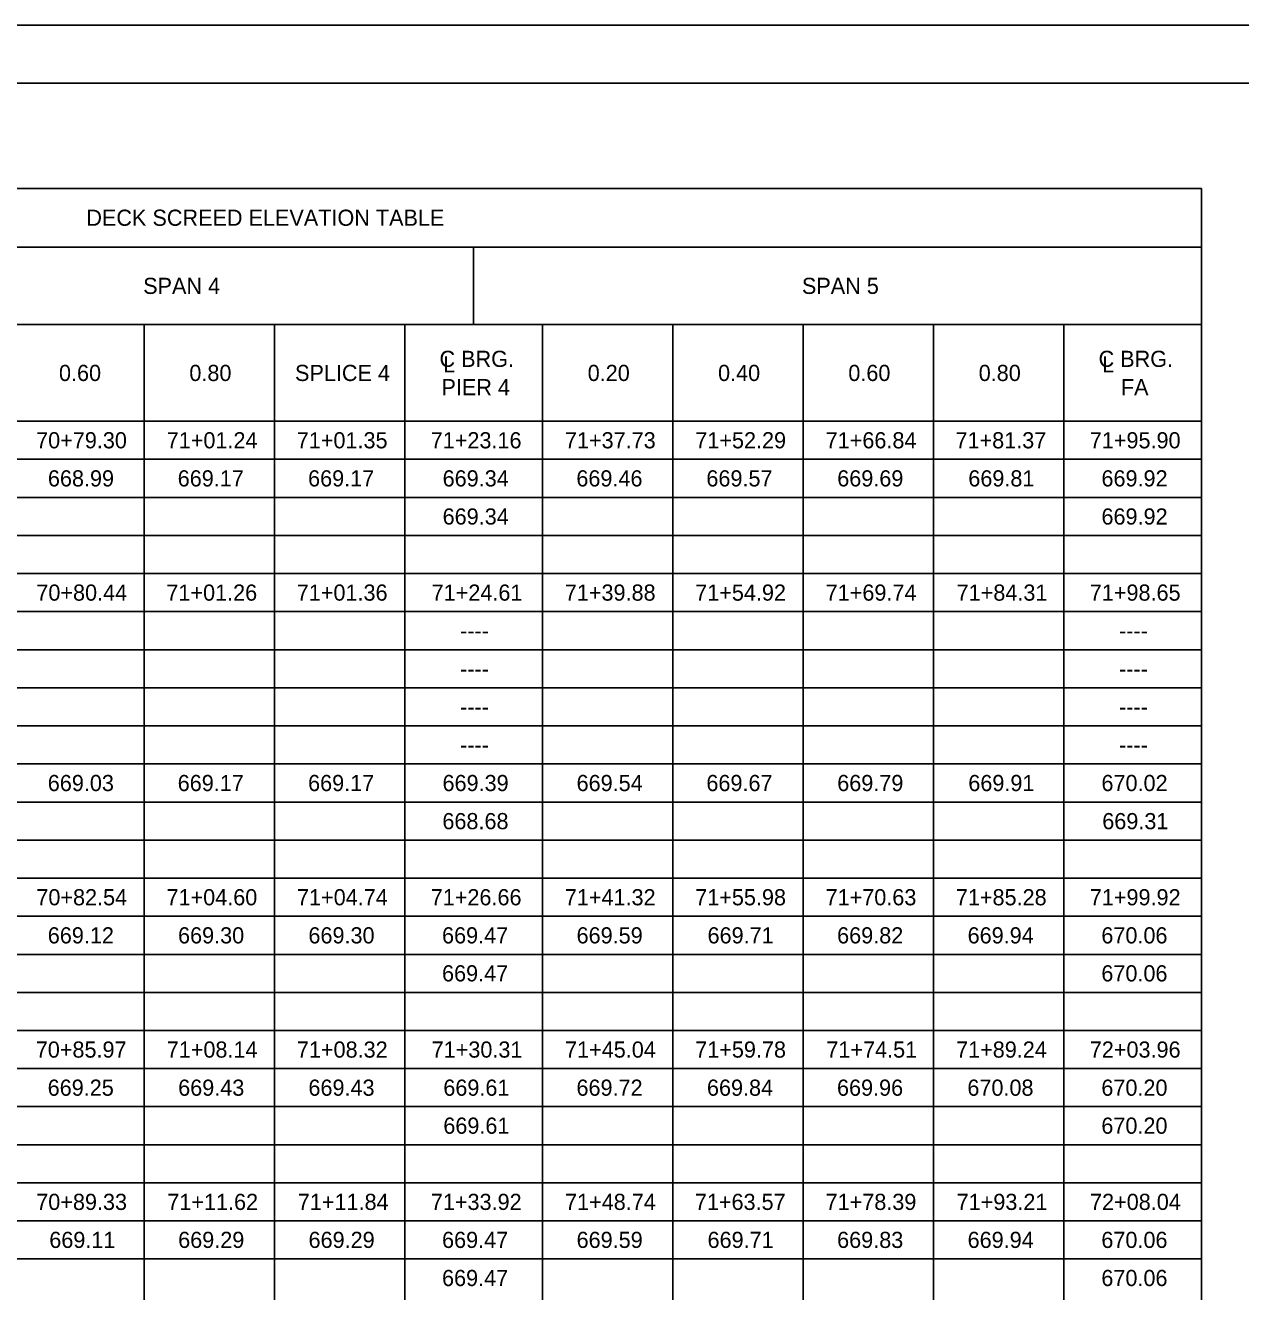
# Model space of a CAD drawing. Extents: x 0 to 34, y 0 to 22.
# Drawn here: x 9.87 to 20.39, y 11.03 to 22 of the extents above; entities that cross this region are included whole.
import ezdxf

# ---------------------------------------------------------------- set-up
doc = ezdxf.new("R2010")
doc.units = 0
for name, color, linetype in [('SH_Border', 7, 'Continuous'), ('SH_Cut_Line', 7, 'Continuous'), ('SH_Text', 7, 'Continuous')]:
    doc.layers.add(name, color=color, linetype=linetype)

msp = doc.modelspace()

# ---------------------------------------------------------------- linework, layer by layer
at = {"layer": 'SH_Border'}
msp.add_lwpolyline([(1.5, 21.5), (33.5, 21.5), (33.5, 0.5), (1.5, 0.5)], close=True, dxfattribs=at)
at = {"layer": 'SH_Cut_Line'}
msp.add_lwpolyline([(0, 0), (34, 0), (34, 22), (0, 22)], close=True, dxfattribs=at)
at = {"layer": 'SH_Text'}
for p, q in [((3.627, 20.588), (20.049, 20.588)), ((20.049, 20.588), (20.049, 1.756)), ((3.627, 20.08), (20.049, 20.08)), ((13.747, 20.08), (13.747, 19.408)), ((3.627, 19.408), (20.049, 19.408)), ((10.894, 19.408), (10.894, 1.756)), ((12.022, 19.408), (12.022, 1.756)), ((13.151, 19.408), (13.151, 1.756)), ((14.343, 19.408), (14.343, 1.756)), ((15.471, 19.408), (15.471, 1.756)), ((16.6, 19.408), (16.6, 1.756)), ((17.729, 19.408), (17.729, 1.756)), ((18.857, 19.408), (18.857, 1.756)), ((3.627, 18.571), (20.049, 18.571)), ((5.022, 18.242), (20.049, 18.242)), ((5.022, 17.912), (20.049, 17.912)), ((3.627, 17.582), (20.049, 17.582)), ((3.627, 17.253), (20.049, 17.253)), ((5.022, 16.923), (20.049, 16.923)), ((5.022, 16.593), (20.049, 16.593)), ((5.022, 16.263), (20.049, 16.263)), ((5.022, 15.934), (20.049, 15.934)), ((5.022, 15.604), (20.049, 15.604)), ((5.022, 15.274), (20.049, 15.274)), ((3.627, 14.945), (20.049, 14.945)), ((3.627, 14.615), (20.049, 14.615)), ((5.022, 14.285), (20.049, 14.285)), ((5.022, 13.955), (20.049, 13.955)), ((3.627, 13.626), (20.049, 13.626)), ((3.627, 13.296), (20.049, 13.296)), ((5.022, 12.966), (20.049, 12.966)), ((5.022, 12.637), (20.049, 12.637)), ((3.627, 12.307), (20.049, 12.307)), ((3.627, 11.977), (20.049, 11.977)), ((5.022, 11.647), (20.049, 11.647)), ((5.022, 11.318), (20.049, 11.318))]:
    msp.add_line(p, q, dxfattribs=at)

# ---------------------------------------------------------------- texts
for s, p in [('DECK SCREED ELEVATION TABLE', (10.394, 20.264)), ('SPAN 4', (10.886, 19.674)), ('SPAN 5', (16.59, 19.674)), ('C BRG.         ', (13.452, 19.042)), ('L', (13.483, 18.995)), ('C BRG.         ', (19.159, 19.042)), ('L', (19.19, 18.995)), ('0.60', (10.157, 18.92)), ('0.80', (11.286, 18.92)), ('SPLICE 4', (12.201, 18.92)), ('0.20', (14.735, 18.92)), ('0.40', (15.864, 18.92)), ('0.60', (16.992, 18.92)), ('0.80', (18.121, 18.92)), ('PIER 4', (13.469, 18.797)), ('FA', (19.352, 18.797)), ('70+79.30', (9.959, 18.337)), ('71+01.24', (11.09, 18.337)), ('71+01.35', (12.216, 18.337)), ('71+23.16', (13.376, 18.337)), ('71+37.73', (14.538, 18.337)), ('71+52.29', (15.667, 18.337)), ('71+66.84', (16.796, 18.337)), ('71+81.37', (17.92, 18.337)), ('71+95.90', (19.083, 18.337)), ('668.99', (10.061, 18.007)), ('669.17', (11.185, 18.007)), ('669.17', (12.314, 18.007)), ('669.34', (13.479, 18.007)), ('669.46', (14.637, 18.007)), ('669.57', (15.763, 18.007)), ('669.69', (16.896, 18.007)), ('669.81', (18.031, 18.007)), ('669.92', (19.184, 18.007)), ('669.34', (13.479, 17.677)), ('669.92', (19.184, 17.677)), ('70+80.44', (9.961, 17.018)), ('71+01.26', (11.087, 17.018)), ('71+01.36', (12.216, 17.018)), ('71+24.61', (13.384, 17.018)), ('71+39.88', (14.537, 17.018)), ('71+54.92', (15.666, 17.018)), ('71+69.74', (16.796, 17.018)), ('71+84.31', (17.93, 17.018)), ('71+98.65', (19.083, 17.018)), ('----', (13.63, 16.688)), ('----', (19.336, 16.688)), ('----', (13.63, 16.358)), ('----', (19.336, 16.358)), ('----', (13.63, 16.029)), ('----', (19.336, 16.029)), ('----', (13.63, 15.699)), ('----', (19.336, 15.699)), ('669.03', (10.06, 15.369)), ('669.17', (11.185, 15.369)), ('669.17', (12.314, 15.369)), ('669.39', (13.478, 15.369)), ('669.54', (14.639, 15.369)), ('669.67', (15.763, 15.369)), ('669.79', (16.896, 15.369)), ('669.91', (18.031, 15.369)), ('670.02', (19.184, 15.369)), ('668.68', (13.477, 15.039)), ('669.31', (19.191, 15.039)), ('70+82.54', (9.961, 14.38)), ('71+04.60', (11.088, 14.38)), ('71+04.74', (12.218, 14.38)), ('71+26.66', (13.376, 14.38)), ('71+41.32', (14.537, 14.38)), ('71+55.98', (15.666, 14.38)), ('71+70.63', (16.795, 14.38)), ('71+85.28', (17.923, 14.38)), ('71+99.92', (19.083, 14.38)), ('669.12', (10.06, 14.05)), ('669.30', (11.188, 14.05)), ('669.30', (12.317, 14.05)), ('669.47', (13.474, 14.05)), ('669.59', (14.639, 14.05)), ('669.71', (15.773, 14.05)), ('669.82', (16.895, 14.05)), ('669.94', (18.025, 14.05)), ('670.06', (19.183, 14.05)), ('669.47', (13.474, 13.721)), ('670.06', (19.183, 13.721)), ('70+85.97', (9.956, 13.061)), ('71+08.14', (11.09, 13.061)), ('71+08.32', (12.217, 13.061)), ('71+30.31', (13.384, 13.061)), ('71+45.04', (14.539, 13.061)), ('71+59.78', (15.666, 13.061)), ('71+74.51', (16.802, 13.061)), ('71+89.24', (17.925, 13.061)), ('72+03.96', (19.083, 13.061)), ('669.25', (10.059, 12.731)), ('669.43', (11.189, 12.731)), ('669.43', (12.317, 12.731)), ('669.61', (13.485, 12.731)), ('669.72', (14.638, 12.731)), ('669.84', (15.768, 12.731)), ('669.96', (16.894, 12.731)), ('670.08', (18.023, 12.731)), ('670.20', (19.183, 12.731)), ('669.61', (13.485, 12.402)), ('670.20', (19.183, 12.402)), ('70+89.33', (9.96, 11.742)), ('71+11.62', (11.095, 11.742)), ('71+11.84', (12.225, 11.742)), ('71+33.92', (13.377, 11.742)), ('71+48.74', (14.539, 11.742)), ('71+63.57', (15.663, 11.742)), ('71+78.39', (16.795, 11.742)), ('71+93.21', (17.93, 11.742)), ('72+08.04', (19.085, 11.742)), ('669.11', (10.073, 11.413)), ('669.29', (11.189, 11.413)), ('669.29', (12.318, 11.413)), ('669.47', (13.474, 11.413)), ('669.59', (14.639, 11.413)), ('669.71', (15.773, 11.413)), ('669.83', (16.895, 11.413)), ('669.94', (18.025, 11.413)), ('670.06', (19.183, 11.413)), ('669.47', (13.474, 11.083)), ('670.06', (19.183, 11.083))]:
    msp.add_text(s, height=0.14, dxfattribs=at).set_placement(p)

doc.saveas('drawing.dxf')
